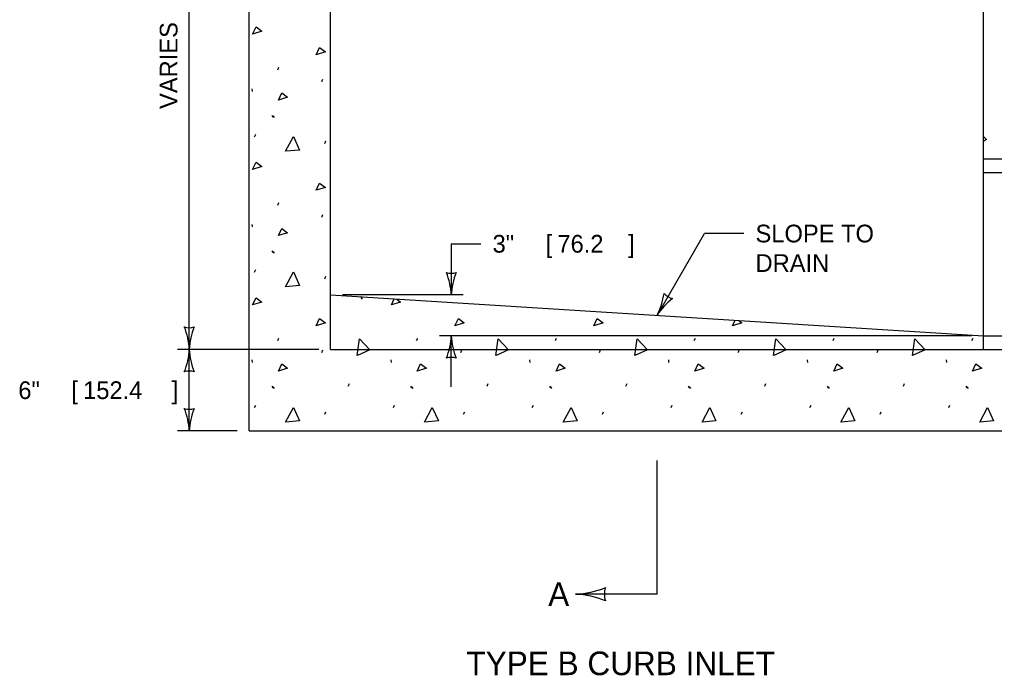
# Model space of a CAD drawing. Extents: x 49991.4 to 50057, y 49987.6 to 50011.4.
# Drawn here: x 50041.919 to 50045.224, y 49993.743 to 49995.965 of the extents above; entities that cross this region are included whole.
import ezdxf

# ---------------------------------------------------------------- set-up
doc = ezdxf.new("R2010")
doc.units = 0
for name, color, linetype in [('Level 1', 7, 'Continuous'), ('Level 2', 7, 'Continuous'), ('Level 3', 7, 'Continuous'), ('Level 6', 7, 'Continuous')]:
    doc.layers.add(name, color=color, linetype=linetype)

msp = doc.modelspace()

# ---------------------------------------------------------------- linework, layer by layer
at = {"layer": 'Level 1'}
for p, q in [((50042.6975, 49994.5712), (50042.6975, 49997.0601)), ((50042.974, 49994.8477), (50042.974, 49996.7836)), ((50045.1865, 49994.8477), (50045.1865, 49996.7836)), ((50042.7948, 49995.7951), (50042.7987, 49995.804)), ((50042.9441, 49995.7548), (50042.948, 49995.7637)), ((50042.7071, 49995.7302), (50042.7081, 49995.7213)), ((50042.7741, 49995.6409), (50042.7781, 49995.635)), ((50042.7781, 49995.6386), (50042.782, 49995.6328)), ((50042.7162, 49995.5681), (50042.7201, 49995.5769)), ((50042.9539, 49995.5455), (50042.9579, 49995.5543)), ((50045.1865, 49995.493), (50045.7396, 49995.493)), ((50045.1865, 49995.4469), (50045.7396, 49995.4469)), ((50042.7948, 49995.3362), (50042.7987, 49995.3451)), ((50042.9441, 49995.296), (50042.948, 49995.3048)), ((50042.7071, 49995.2713), (50042.7081, 49995.2625)), ((50042.7741, 49995.182), (50042.7781, 49995.1761)), ((50042.7781, 49995.1798), (50042.782, 49995.1739)), ((50042.7162, 49995.1092), (50042.7201, 49995.118)), ((50042.9539, 49995.0866), (50042.9579, 49995.0954)), ((50042.974, 49995.0321), (50045.1865, 49994.8938)), ((50043.0767, 49995.0237), (50043.0806, 49995.0178)), ((50043.1799, 49994.9982), (50043.1897, 49995.0186)), ((50044.3363, 49994.928), (50044.3452, 49994.9464)), ((50045.1865, 49994.8938), (50045.7396, 49994.8938)), ((50042.7948, 49994.8774), (50042.7987, 49994.8862)), ((50043.2653, 49994.8774), (50043.2693, 49994.8862)), ((50043.7359, 49994.8774), (50043.7398, 49994.8862)), ((50044.2065, 49994.8774), (50044.2104, 49994.8862)), ((50044.677, 49994.8774), (50044.6809, 49994.8862)), ((50045.1476, 49994.8774), (50045.1515, 49994.8862)), ((50042.9441, 49994.8371), (50042.948, 49994.8459)), ((50042.974, 49994.8477), (50045.1865, 49994.8477)), ((50043.4147, 49994.8371), (50043.4186, 49994.8459)), ((50043.8852, 49994.8371), (50043.8891, 49994.8459)), ((50044.3558, 49994.8371), (50044.3597, 49994.8459)), ((50044.8263, 49994.8371), (50044.8302, 49994.8459)), ((50045.1865, 49994.8477), (50045.7396, 49994.8477)), ((50042.7071, 49994.8124), (50042.7081, 49994.8036)), ((50043.1777, 49994.8124), (50043.1786, 49994.8036)), ((50043.6482, 49994.8124), (50043.6492, 49994.8036)), ((50044.1188, 49994.8124), (50044.1197, 49994.8036)), ((50044.5893, 49994.8124), (50044.5903, 49994.8036)), ((50045.0599, 49994.8124), (50045.0609, 49994.8036)), ((50042.7741, 49994.7231), (50042.7781, 49994.7172)), ((50043.0335, 49994.7231), (50043.0374, 49994.732)), ((50043.2447, 49994.7231), (50043.2486, 49994.7172)), ((50043.504, 49994.7231), (50043.508, 49994.732)), ((50043.7153, 49994.7231), (50043.7192, 49994.7172)), ((50043.9746, 49994.7231), (50043.9785, 49994.732)), ((50044.1858, 49994.7231), (50044.1897, 49994.7172)), ((50044.4452, 49994.7231), (50044.4491, 49994.732)), ((50044.6564, 49994.7231), (50044.6603, 49994.7172)), ((50044.9157, 49994.7231), (50044.9196, 49994.732)), ((50045.1269, 49994.7231), (50045.1309, 49994.7172)), ((50042.7781, 49994.7209), (50042.782, 49994.715)), ((50043.2486, 49994.7209), (50043.2526, 49994.715)), ((50043.7192, 49994.7209), (50043.7231, 49994.715)), ((50044.1897, 49994.7209), (50044.1937, 49994.715)), ((50044.6603, 49994.7209), (50044.6642, 49994.715)), ((50045.1309, 49994.7209), (50045.1348, 49994.715)), ((50042.7162, 49994.6503), (50042.7201, 49994.6592)), ((50043.1867, 49994.6503), (50043.1907, 49994.6592)), ((50043.6573, 49994.6503), (50043.6612, 49994.6592)), ((50044.1278, 49994.6503), (50044.1318, 49994.6592)), ((50044.5984, 49994.6503), (50044.6023, 49994.6592)), ((50045.069, 49994.6503), (50045.0729, 49994.6592)), ((50042.9539, 49994.6277), (50042.9579, 49994.6366)), ((50043.4245, 49994.6277), (50043.4284, 49994.6366)), ((50043.895, 49994.6277), (50043.899, 49994.6366)), ((50044.3656, 49994.6277), (50044.3695, 49994.6366)), ((50044.8361, 49994.6277), (50044.8401, 49994.6366)), ((50042.6975, 49994.5712), (50045.463, 49994.5712))]:
    msp.add_line(p, q, dxfattribs=at)
for points in [[(50042.7093, 49995.9159), (50042.7211, 49995.9405), (50042.7407, 49995.9258), (50042.7093, 49995.9159)], [(50042.9246, 49995.8457), (50042.9364, 49995.8703), (50042.9561, 49995.8555), (50042.9246, 49995.8457)], [(50042.7968, 49995.692), (50042.8085, 49995.7165), (50042.8282, 49995.7018), (50042.7968, 49995.692)], [(50042.8213, 49995.519), (50042.8478, 49995.5691), (50042.8685, 49995.5229), (50042.8223, 49995.519)], [(50045.1865, 49995.5695), (50045.1973, 49995.5584), (50045.1865, 49995.5534)], [(50042.7093, 49995.4571), (50042.7211, 49995.4816), (50042.7407, 49995.4669), (50042.7093, 49995.4571)], [(50042.9246, 49995.3868), (50042.9364, 49995.4114), (50042.9561, 49995.3967), (50042.9246, 49995.3868)], [(50042.7968, 49995.2331), (50042.8085, 49995.2577), (50042.8282, 49995.2429), (50042.7968, 49995.2331)], [(50042.8213, 49995.0601), (50042.8478, 49995.1102), (50042.8685, 49995.064), (50042.8223, 49995.0601)], [(50042.7093, 49994.9982), (50042.7211, 49995.0228), (50042.7407, 49995.008), (50042.7093, 49994.9982)], [(50043.1979, 49995.0181), (50043.2113, 49995.008), (50043.1799, 49994.9982)], [(50042.9246, 49994.928), (50042.9364, 49994.9525), (50042.9561, 49994.9378), (50042.9246, 49994.928)], [(50043.3952, 49994.928), (50043.407, 49994.9525), (50043.4266, 49994.9378), (50043.3952, 49994.928)], [(50043.8658, 49994.928), (50043.8775, 49994.9525), (50043.8972, 49994.9378), (50043.8658, 49994.928)], [(50044.3573, 49994.9456), (50044.3677, 49994.9378), (50044.3363, 49994.928)], [(50043.0636, 49994.8269), (50043.0714, 49994.8831), (50043.1066, 49994.8467), (50043.0645, 49994.8273)], [(50043.5342, 49994.8269), (50043.542, 49994.8831), (50043.5771, 49994.8467), (50043.5351, 49994.8273)], [(50044.0047, 49994.8269), (50044.0125, 49994.8831), (50044.0477, 49994.8467), (50044.0056, 49994.8273)], [(50044.4753, 49994.8269), (50044.4831, 49994.8831), (50044.5182, 49994.8467), (50044.4762, 49994.8273)], [(50044.9458, 49994.8269), (50044.9536, 49994.8831), (50044.9888, 49994.8467), (50044.9467, 49994.8273)], [(50042.7968, 49994.7742), (50042.8085, 49994.7988), (50042.8282, 49994.784), (50042.7968, 49994.7742)], [(50043.2673, 49994.7742), (50043.2791, 49994.7988), (50043.2987, 49994.784), (50043.2673, 49994.7742)], [(50043.7379, 49994.7742), (50043.7496, 49994.7988), (50043.7693, 49994.784), (50043.7379, 49994.7742)], [(50044.2084, 49994.7742), (50044.2202, 49994.7988), (50044.2398, 49994.784), (50044.2084, 49994.7742)], [(50044.679, 49994.7742), (50044.6908, 49994.7988), (50044.7104, 49994.784), (50044.679, 49994.7742)], [(50045.1495, 49994.7742), (50045.1613, 49994.7988), (50045.181, 49994.784), (50045.1495, 49994.7742)], [(50042.8213, 49994.6012), (50042.8478, 49994.6513), (50042.8685, 49994.6051), (50042.8223, 49994.6012)], [(50043.2919, 49994.6012), (50043.3184, 49994.6513), (50043.339, 49994.6051), (50043.2928, 49994.6012)], [(50043.7624, 49994.6012), (50043.7889, 49994.6513), (50043.8096, 49994.6051), (50043.7634, 49994.6012)], [(50044.233, 49994.6012), (50044.2595, 49994.6513), (50044.2801, 49994.6051), (50044.234, 49994.6012)], [(50044.7035, 49994.6012), (50044.7301, 49994.6513), (50044.7507, 49994.6051), (50044.7045, 49994.6012)], [(50045.1741, 49994.6012), (50045.2006, 49994.6513), (50045.2212, 49994.6051), (50045.1751, 49994.6012)]]:
    msp.add_lwpolyline(points, dxfattribs=at)
at = {"layer": 'Level 3'}
for p, q in [((50042.4948, 49994.8477), (50042.4948, 49996.3979)), ((50044.0803, 49994.9629), (50044.2415, 49995.2402)), ((50044.3742, 49995.2402), (50044.2415, 49995.2402)), ((50043.3829, 49995.2055), (50043.3829, 49995.0321)), ((50043.3829, 49995.2055), (50043.4829, 49995.2055)), ((50043.4229, 49995.0321), (50043.014, 49995.0321)), ((50045.1465, 49994.8938), (50043.343, 49994.8938)), ((50043.3829, 49994.7204), (50043.3829, 49994.8938)), ((50042.934, 49994.8477), (50042.4548, 49994.8477)), ((50042.4948, 49994.5712), (50042.4948, 49994.8477)), ((50042.6575, 49994.5712), (50042.4548, 49994.5712))]:
    msp.add_line(p, q, dxfattribs=at)
for centre, radius, start, end in [((50043.3829, 49995.1603), 0.0548, 252.1388, 287.8612), ((50043.1502, 49995.0206), 0.233, 2.8273, 22.0772), ((50043.6051, 49995.0229), 0.2223, 157.456, 177.6395), ((50043.8733, 49995.07), 0.233, 332.6445, 351.8944), ((50044.2677, 49994.8434), 0.2223, 127.2732, 147.4568), ((50044.1447, 49995.0738), 0.0548, 221.9561, 257.6784), ((50042.4948, 49994.9759), 0.0548, 252.1388, 287.8612), ((50042.2621, 49994.8362), 0.233, 2.8273, 22.0772), ((50042.7169, 49994.8386), 0.2223, 157.456, 177.6395), ((50043.1608, 49994.903), 0.2223, 337.456, 357.6395), ((50043.6156, 49994.9053), 0.233, 182.8273, 202.0772), ((50042.2727, 49994.8569), 0.2223, 337.456, 357.6395), ((50042.7275, 49994.8592), 0.233, 182.8273, 202.0772), ((50043.3829, 49994.7656), 0.0548, 72.1388, 107.8612), ((50042.4948, 49994.7195), 0.0548, 72.1388, 107.8612), ((50042.4948, 49994.6994), 0.0548, 252.1388, 287.8612), ((50042.2621, 49994.5597), 0.233, 2.8273, 22.0772), ((50042.7169, 49994.562), 0.2223, 157.456, 177.6395)]:
    msp.add_arc(centre, radius, start, end, dxfattribs=at)
at = {"layer": 'Level 6'}
for q in [(50044.0803, 49994.4712), (50043.8037, 49994.0181)]:
    msp.add_line((50044.0803, 49994.0181), q, dxfattribs=at)
msp.add_lwpolyline([(50043.8037, 49994.0181), (50043.8037, 49994.0181)], dxfattribs=at)
for centre, radius, start, end in [((50043.7884, 49994.3283), 0.3107, 272.8273, 292.0772), ((50043.9747, 49994.0181), 0.073, 162.1388, 197.8612), ((50043.7915, 49993.7219), 0.2964, 67.456, 87.6395)]:
    msp.add_arc(centre, radius, start, end, dxfattribs=at)

# ---------------------------------------------------------------- texts
at = {"layer": 'Level 2'}
for s, rotation, p in [('VARIES', 90, (50042.4548, 49995.6622)), ('3" ', 360, (50043.5229, 49995.1755)), ('[', 360, (50043.7029, 49995.1755)), ('76.2', 360, (50043.7426, 49995.1755)), (']', 360, (50043.9826, 49995.1755))]:
    msp.add_text(s, height=0.06, rotation=rotation, dxfattribs=at).set_placement(p)
for s, height, p in [('SLOPE TO ', 0.06, (50044.4142, 49995.2102)), ('DRAIN', 0.06, (50044.4142, 49995.1102)), ('6" ', 0.06, (50041.9153, 49994.6794)), ('[', 0.06, (50042.0953, 49994.6794)), ('152.4', 0.06, (50042.135, 49994.6794)), (']', 0.06, (50042.435, 49994.6794)), ('A', 0.08, (50043.7114, 49993.9781)), ('TYPE B CURB INLET', 0.08, (50043.4341, 49993.7439))]:
    msp.add_text(s, height=height, dxfattribs=at).set_placement(p)

doc.saveas('drawing.dxf')
